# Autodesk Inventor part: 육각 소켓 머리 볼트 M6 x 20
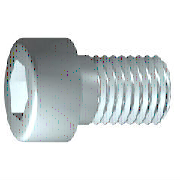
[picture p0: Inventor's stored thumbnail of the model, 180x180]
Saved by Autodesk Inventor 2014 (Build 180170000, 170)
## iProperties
IsCustomPart: 1
Created: 2012-02
Part Number: 육각 소켓 머리 볼트 M6 x 20
Material: 강철, 연강
Description: 6각 소켓 머리 캡 나사
Document SubType Name: Modeling
Standard: ISO 4762
Designer: mdu-01
Standard Revision: Fourth edition 2004-03-01
Standards Organization: ISO
Language: ko-KR
Size Designation: M6 x 20
Categories: <MemberInstance><Categories><Category DisplayName="조임쇠" InternalName="e4da775c-781d-43d5-af7c-5136215cf5a6" Mnemonic="FSTN"><Category DisplayName="볼트" InternalN
Density: 7.75 g/cm^3
Appearance: 강철
Author: mdu-01
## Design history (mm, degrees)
sketch "스케치1"
  geometry: L1 (-1.333, 0)-(20, 0); L2 (20, 0)-(20, 3); L3 (20, 3)-(2.5, 3); L4 (2.5, 3)-(1.886, 3); L5 (1.886, 3)-(0, 3); L6 (0, 3)-(0, 5); L7 (0, 5)-(-6, 5); L8 (-6, 5)-(-6, 2.887); L9 (-6, 2.887)-(-3, 2.887); L10 (-3, 2.887)-(-1.333, 0); L11 (-11.2, 0)-(25.2, 0) reference; L12 (0, -1)-(0, 6) reference; L13 (2.5, 3)-(0, 3)
  constraints: 22 end point, 6 parallel, 2 collinear, 2 perpendicular, 1 horizontal, 1 point on line
  dimensions: "d1" = 17.5 distance from line of L3.end L2 (= GEL); "d2" = 0.61355 distance of L4.end L3.end (computed from GAL); "d3" = 6 distance between parallel lines of L8 L6 (= KOH); "d4" = 3 distance of L8.end L9.end (= INTI); "d5" = 60 deg angle of L10 L1; "d6" = 6 diameter of L3 L1 (= GD); "d7" = 6 diameter of L5 L1 (= BDM); "d8" = 5.7735 diameter of L9 L1 (= 1.1547 x SW); "d9" = 10 diameter of L7 L1 (= KOD); "d26" = 20 distance between parallel lines of L12 L2 (= NLG)
revolve "본체" sketch "스케치1" stored, may be unused: angle "d10" = 90 deg
sketch "스케치2"
  geometry: L1 (0, -7)-(0, 7) reference; L2 (-7, 0)-(7, 0) reference; L3 (2.887, 0)-(1.443, -2.5); L4 (1.443, -2.5)-(-1.443, -2.5); L5 (-1.443, -2.5)-(-2.887, 0); L6 (-2.887, 0)-(-1.443, 2.5); L7 (-1.443, 2.5)-(1.443, 2.5); L8 (1.443, 2.5)-(2.887, 0); 2 further points
  constraints: 12 end point, 1 coincident, 1 horizontal alignment, 1 point on line, 12 other
extrude "슬롯" join sketch "스케치2" stored distance "d11" = 10; taper "d12" = 0 deg
workplane "Work Plane1"
fillet "Fillet2" dims "d30" = 0.1 (= R)
body "Solid1"
fillet "모깎기1" dims "d17" = 0.6 (= RR)
feature "스레드" dims "d13" = 17.5 (= GEL), "d14" = 0
chamfer "모따기1" distance "d15" = 0.61345 (= -0.5 x SPD + 0.5 x GD); stored, may be unused: second distance "d16" = 0.61345 (= GUL), angle "d27" = 45 deg
other parameters: "GD" = 6 [user parameter; used in 2 equation terms], "NLG" = 20 [user parameter; used in 1 equation term], "GEL" = 17.5 [user parameter; used in 2 equation terms], "KOD" = 10 [user parameter; used in 1 equation term], "KOH" = 6 [user parameter; used in 1 equation term], "INTI" = 3 [user parameter; used in 1 equation term], "GAL" = 0.61345 (= 0.61345 x PTC) [user parameter; used in 1 equation term], "GUL" = 0.61345 (= 0.61345 x PTC) [user parameter; used in 1 equation term], "BDM" = 6 (= NND) [user parameter; used in 1 equation term], "SW" = 5 [user parameter; used in 2 equation terms], "RR" = 0.6 [user parameter; used in 1 equation term], "SPD" = 4.7731 (= NND - 1.2269 x PTC) [user parameter; used in 1 equation term], "d19" = 0, "d28" = 0, "d29" = 0, "R" = 0.1 [user parameter; used in 1 equation term], "TOA" = 30 deg [user parameter], "GD1" = 4.7731 (= THREADDIA - 1.2269 x PTC) [user parameter], "THREADDIA" = 6 [user parameter; used in 1 equation term], "FAWI" = 45 deg [user parameter], "PTC" = 1 [user parameter; used in 5 equation terms], "NND" = 6 [user parameter; used in 2 equation terms], "E0" = 5.775 (= 1.155 x SW) [user parameter]
